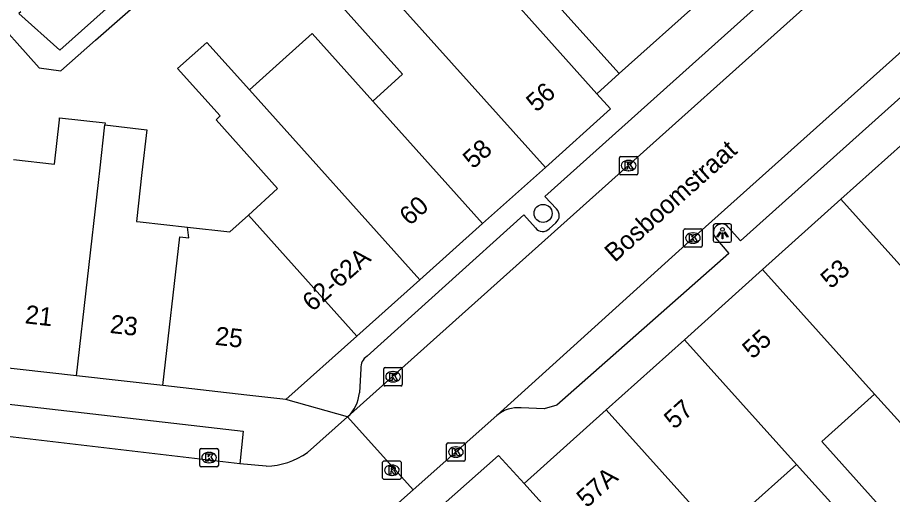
# Model space of a CAD drawing. Extents: x 162172 to 163187, y 382874 to 383684.
# Drawn here: x 162715.53 to 162762.94, y 383404.94 to 383430.81 of the extents above; entities that cross this region are included whole.
import ezdxf

# ---------------------------------------------------------------- set-up
doc = ezdxf.new("R2010")
doc.units = 0
for name, color, linetype in [('IMGEO_Boom', 7, 'Continuous'), ('IMGEO_Hek', 7, 'Continuous'), ('IMGEO_Kolk', 7, 'Continuous'), ('IMGEO_Lichtpunt', 7, 'Continuous'), ('IMGEO_Openbare_ruimte_label', 7, 'Continuous'), ('IMGEO_Pand', 7, 'Continuous'), ('IMGEO_Pand_nummerreeks', 7, 'Continuous'), ('IMGEO_Rijbaan_lokaal_open', 7, 'Continuous'), ('IMGEO_Rioolput', 7, 'Continuous'), ('IMGEO_Voetpad_open', 7, 'Continuous')]:
    doc.layers.add(name, color=color, linetype=linetype)

msp = doc.modelspace()

# ---------------------------------------------------------------- linework, layer by layer
at = {"layer": 'IMGEO_Boom'}
msp.add_circle((162744.01, 383420.19), 0.489, dxfattribs=at)
at = {"layer": 'IMGEO_Hek'}
msp.add_lwpolyline([(162746.923, 383426.68), (162748.132, 383427.77)], dxfattribs=at)
at = {"layer": 'IMGEO_Kolk'}
for p, q in [((162748.144, 383422.354), (162748.144, 383423.206)), ((162748.219, 383423.28), (162749.071, 383423.28)), ((162748.632, 383423.06), (162748.657, 383423.06)), ((162749.145, 383423.206), (162749.145, 383422.354)), ((162749.071, 383422.28), (162748.219, 383422.28)), ((162748.655, 383422.5), (162748.63, 383422.5)), ((162751.628, 383418.426), (162751.628, 383419.278)), ((162751.703, 383419.352), (162752.555, 383419.352)), ((162752.629, 383419.278), (162752.629, 383418.426)), ((162752.116, 383419.132), (162752.141, 383419.132)), ((162752.555, 383418.352), (162751.703, 383418.352)), ((162752.139, 383418.572), (162752.114, 383418.572)), ((162735.383, 383410.903), (162735.383, 383411.755)), ((162735.458, 383411.829), (162736.31, 383411.829)), ((162736.384, 383411.755), (162736.384, 383410.903)), ((162735.871, 383411.609), (162735.896, 383411.609)), ((162736.31, 383410.829), (162735.458, 383410.829)), ((162735.894, 383411.049), (162735.869, 383411.049)), ((162725.415, 383406.52), (162725.415, 383407.372)), ((162725.49, 383407.446), (162726.342, 383407.446)), ((162726.416, 383407.372), (162726.416, 383406.52)), ((162738.785, 383406.822), (162738.785, 383407.674)), ((162738.86, 383407.748), (162739.712, 383407.748)), ((162739.273, 383407.528), (162739.298, 383407.528)), ((162739.786, 383407.674), (162739.786, 383406.822)), ((162725.903, 383407.226), (162725.928, 383407.226)), ((162739.296, 383406.968), (162739.271, 383406.968)), ((162726.342, 383406.446), (162725.49, 383406.446)), ((162725.926, 383406.666), (162725.901, 383406.666)), ((162739.712, 383406.748), (162738.86, 383406.748))]:
    msp.add_line(p, q, dxfattribs=at)
for points in [[(162748.144, 383422.354), (162748.144, 383423.206)], [(162748.219, 383423.28), (162749.071, 383423.28)], [(162749.145, 383423.206), (162749.145, 383422.354)], [(162748.465, 383422.98), (162748.588, 383422.98), (162748.588, 383422.829), (162748.718, 383422.98), (162748.882, 383422.98), (162748.736, 383422.829), (162748.889, 383422.58), (162748.737, 383422.58), (162748.652, 383422.744), (162748.588, 383422.677), (162748.588, 383422.58), (162748.465, 383422.58), (162748.465, 383422.98)], [(162749.071, 383422.28), (162748.219, 383422.28)], [(162751.628, 383418.426), (162751.628, 383419.278)], [(162751.703, 383419.352), (162752.555, 383419.352)], [(162752.629, 383419.278), (162752.629, 383418.426)], [(162751.949, 383419.052), (162752.072, 383419.052), (162752.072, 383418.901), (162752.202, 383419.052), (162752.366, 383419.052), (162752.22, 383418.901), (162752.373, 383418.652), (162752.221, 383418.652), (162752.136, 383418.816), (162752.072, 383418.749), (162752.072, 383418.652), (162751.949, 383418.652), (162751.949, 383419.052)], [(162752.555, 383418.352), (162751.703, 383418.352)], [(162735.383, 383410.903), (162735.383, 383411.755)], [(162735.458, 383411.829), (162736.31, 383411.829)], [(162736.384, 383411.755), (162736.384, 383410.903)], [(162735.704, 383411.529), (162735.827, 383411.529), (162735.827, 383411.378), (162735.957, 383411.529), (162736.121, 383411.529), (162735.975, 383411.378), (162736.128, 383411.129), (162735.976, 383411.129), (162735.891, 383411.293), (162735.827, 383411.226), (162735.827, 383411.129), (162735.704, 383411.129), (162735.704, 383411.529)], [(162736.31, 383410.829), (162735.458, 383410.829)], [(162725.415, 383406.52), (162725.415, 383407.372)], [(162725.49, 383407.446), (162726.342, 383407.446)], [(162726.416, 383407.372), (162726.416, 383406.52)], [(162738.785, 383406.822), (162738.785, 383407.674)], [(162738.86, 383407.748), (162739.712, 383407.748)], [(162739.106, 383407.448), (162739.229, 383407.448), (162739.229, 383407.297), (162739.359, 383407.448), (162739.523, 383407.448), (162739.377, 383407.297), (162739.53, 383407.048), (162739.378, 383407.048), (162739.293, 383407.212), (162739.229, 383407.145), (162739.229, 383407.048), (162739.106, 383407.048), (162739.106, 383407.448)], [(162739.786, 383407.674), (162739.786, 383406.822)], [(162725.736, 383407.146), (162725.859, 383407.146), (162725.859, 383406.995), (162725.989, 383407.146), (162726.153, 383407.146), (162726.007, 383406.995), (162726.16, 383406.746), (162726.008, 383406.746), (162725.923, 383406.91), (162725.859, 383406.843), (162725.859, 383406.746), (162725.736, 383406.746), (162725.736, 383407.146)], [(162726.342, 383406.446), (162725.49, 383406.446)], [(162739.712, 383406.748), (162738.86, 383406.748)]]:
    msp.add_lwpolyline(points, dxfattribs=at)
for centre, start, end in [((162748.221, 383423.204), 91.552, 178.448), ((162748.221, 383423.204), 91.552, 178.448), ((162749.069, 383423.204), 1.552, 88.448), ((162749.069, 383423.204), 1.552, 88.448), ((162748.221, 383422.356), 181.552, 268.448), ((162748.221, 383422.356), 181.552, 268.448), ((162749.069, 383422.356), 271.552, 358.448), ((162749.069, 383422.356), 271.552, 358.448), ((162751.705, 383419.276), 91.552, 178.448), ((162751.705, 383419.276), 91.552, 178.448), ((162752.553, 383419.276), 1.552, 88.448), ((162752.553, 383419.276), 1.552, 88.448), ((162751.705, 383418.428), 181.552, 268.448), ((162751.705, 383418.428), 181.552, 268.448), ((162752.553, 383418.428), 271.552, 358.448), ((162752.553, 383418.428), 271.552, 358.448), ((162735.46, 383411.753), 91.552, 178.448), ((162735.46, 383411.753), 91.552, 178.448), ((162736.308, 383411.753), 1.552, 88.448), ((162736.308, 383411.753), 1.552, 88.448), ((162735.46, 383410.905), 181.552, 268.448), ((162735.46, 383410.905), 181.552, 268.448), ((162736.308, 383410.905), 271.552, 358.448), ((162736.308, 383410.905), 271.552, 358.448), ((162725.492, 383407.37), 91.552, 178.448), ((162725.492, 383407.37), 91.552, 178.448), ((162726.34, 383407.37), 1.552, 88.448), ((162726.34, 383407.37), 1.552, 88.448), ((162738.862, 383407.672), 91.552, 178.448), ((162738.862, 383407.672), 91.552, 178.448), ((162739.71, 383407.672), 1.552, 88.448), ((162739.71, 383407.672), 1.552, 88.448), ((162725.492, 383406.522), 181.552, 268.448), ((162725.492, 383406.522), 181.552, 268.448), ((162726.34, 383406.522), 271.552, 358.448), ((162726.34, 383406.522), 271.552, 358.448), ((162738.862, 383406.824), 181.552, 268.448), ((162738.862, 383406.824), 181.552, 268.448), ((162739.71, 383406.824), 271.552, 358.448), ((162739.71, 383406.824), 271.552, 358.448)]:
    msp.add_arc(centre, 0.0765, start, end, dxfattribs=at)
for centre, major_axis, ratio, start_param, end_param in [((162748.631, 383422.78), (-0.387, 0.002), 0.722429, 4.712389, 7.853982), ((162748.656, 383422.78), (-0.39, 0.002), 0.717154, 1.570796, 4.712389), ((162752.115, 383418.852), (-0.387, 0.002), 0.722429, 4.712389, 7.853982), ((162752.14, 383418.852), (-0.39, 0.002), 0.717154, 1.570796, 4.712389), ((162735.87, 383411.329), (-0.387, 0.002), 0.722429, 4.712389, 7.853982), ((162735.895, 383411.329), (-0.39, 0.002), 0.717154, 1.570796, 4.712389), ((162739.272, 383407.248), (-0.387, 0.002), 0.722429, 4.712389, 7.853982), ((162739.297, 383407.248), (-0.39, 0.002), 0.717154, 1.570796, 4.712389), ((162725.902, 383406.946), (-0.387, 0.002), 0.722429, 4.712389, 7.853982), ((162725.927, 383406.946), (-0.39, 0.002), 0.717154, 1.570796, 4.712389)]:
    msp.add_ellipse(centre, major_axis=major_axis, ratio=ratio, start_param=start_param, end_param=end_param, dxfattribs=at)
at = {"layer": 'IMGEO_Lichtpunt'}
for p, q in [((162753.232, 383419.523), (162753.232, 383418.716)), ((162753.232, 383419.523), (162753.232, 383418.716)), ((162754.134, 383419.618), (162753.326, 383419.618)), ((162754.134, 383419.618), (162753.326, 383419.618)), ((162754.228, 383418.716), (162754.228, 383419.523)), ((162754.228, 383418.716), (162754.228, 383419.523)), ((162753.326, 383418.622), (162754.134, 383418.622)), ((162753.326, 383418.622), (162754.134, 383418.622))]:
    msp.add_line(p, q, dxfattribs=at)
for points in [[(162753.606, 383419.187), (162753.645, 383419.159), (162753.457, 383418.897), (162753.419, 383418.924), (162753.606, 383419.187)], [(162753.708, 383419.139), (162753.755, 383419.139), (162753.755, 383418.817), (162753.708, 383418.817), (162753.708, 383419.139)], [(162753.818, 383419.159), (162753.856, 383419.186), (162754.043, 383418.924), (162754.004, 383418.896), (162753.818, 383419.159)]]:
    msp.add_lwpolyline(points, dxfattribs=at)
msp.add_circle((162753.731, 383419.321), 0.0994, dxfattribs=at)
for centre, start, end in [((162753.326, 383419.523), 90, 180), ((162753.326, 383419.523), 90, 180), ((162754.134, 383419.523), 0, 90), ((162754.134, 383419.523), 0, 90), ((162753.326, 383418.716), 180, 270), ((162753.326, 383418.716), 180, 270), ((162754.134, 383418.716), 270, 0), ((162754.134, 383418.716), 270, 360)]:
    msp.add_arc(centre, 0.0946, start, end, dxfattribs=at)
at = {"layer": 'IMGEO_Pand'}
for points in [[(162748.132, 383427.77), (162742.099, 383434.496)], [(162734.778, 383426.279), (162736.399, 383427.732), (162733.136, 383431.374), (162734.919, 383432.971)], [(162734.919, 383432.971), (162744.135, 383422.684)], [(162741.697, 383432.527), (162744.331, 383429.573), (162746.923, 383426.68)], [(162715.706, 383431.115), (162715.607, 383431.027), (162717.821, 383429.043), (162721.517, 383432.346)], [(162748.132, 383427.77), (162752.658, 383431.842)], [(162728.095, 383426.888), (162729.908, 383428.512), (162731.5, 383429.938), (162734.778, 383426.279)], [(162728.044, 383420.099), (162729.629, 383421.542), (162726.289, 383425.27), (162726.517, 383425.474), (162724.21, 383428.048), (162725.788, 383429.462), (162728.095, 383426.888)], [(162737.328, 383416.585), (162728.095, 383426.888)], [(162744.135, 383422.684), (162747.668, 383425.849), (162746.923, 383426.68)], [(162740.731, 383419.634), (162734.778, 383426.279)], [(162715.325, 383423.104), (162717.531, 383422.854), (162717.804, 383425.263), (162717.817, 383425.378), (162720.286, 383425.098), (162720.273, 383424.984)], [(162718.732, 383411.377), (162719.92, 383421.872), (162720.009, 383422.654), (162720.254, 383424.821), (162720.273, 383424.984)], [(162720.273, 383424.984), (162722.536, 383424.727), (162722.272, 383422.398), (162721.972, 383419.747), (162722.182, 383419.724), (162724.749, 383419.442)], [(162760.149, 383420.951), (162764.392, 383424.759)], [(162740.731, 383419.634), (162744.135, 383422.684)], [(162755.907, 383417.144), (162760.149, 383420.951)], [(162760.149, 383420.951), (162766.217, 383414.192)], [(162724.749, 383419.442), (162727.046, 383419.189), (162728.044, 383420.099)], [(162728.044, 383420.099), (162733.924, 383413.536)], [(162723.408, 383410.848), (162724.321, 383418.91), (162724.816, 383418.854), (162724.749, 383419.442)], [(162737.328, 383416.585), (162740.731, 383419.634)], [(162751.665, 383413.337), (162755.907, 383417.144)], [(162761.975, 383410.385), (162755.907, 383417.144)], [(162733.924, 383413.536), (162737.328, 383416.585)], [(162730.081, 383410.092), (162733.924, 383413.536)], [(162747.423, 383409.529), (162751.665, 383413.337)], [(162757.734, 383406.577), (162751.665, 383413.337)], [(162718.732, 383411.377), (162714.057, 383411.906)], [(162723.408, 383410.848), (162718.732, 383411.377)], [(162730.081, 383410.092), (162727.951, 383410.333), (162723.408, 383410.848)], [(162766.032, 383405.895), (162763.147, 383403.317), (162759.111, 383407.813), (162761.975, 383410.385)], [(162761.975, 383410.385), (162766.032, 383405.895)], [(162742.977, 383405.54), (162747.423, 383409.529)], [(162747.423, 383409.529), (162753.492, 383402.769)], [(162761.781, 383402.098), (162758.895, 383399.52), (162754.869, 383404.005), (162757.734, 383406.577)], [(162757.734, 383406.577), (162761.781, 383402.098)], [(162753.709, 383393.536), (162749.046, 383398.778), (162742.977, 383405.54)]]:
    msp.add_lwpolyline(points, dxfattribs=at)
at = {"layer": 'IMGEO_Rijbaan_lokaal_open'}
for points in [[(162741.498, 383409.238), (162752.129, 383418.852), (162795.051, 383457.315)], [(162772.219, 383443.956), (162733.422, 383409.153), (162733.42, 383409.152)], [(162727.575, 383406.608), (162691.943, 383410.803)], [(162733.42, 383409.152), (162731.239, 383407.228)], [(162733.42, 383409.152), (162736.967, 383405.198)], [(162741.498, 383409.238), (162736.967, 383405.198)], [(162729.014, 383406.474), (162727.575, 383406.608)], [(162736.967, 383405.198), (162733.903, 383402.466)]]:
    msp.add_lwpolyline(points, dxfattribs=at)
msp.add_arc((162728.858, 383410.593), 4.122, 272.1624, 305.2782, dxfattribs=at)
at = {"layer": 'IMGEO_Rioolput'}
for p, q in [((162735.315, 383405.838), (162735.315, 383406.69)), ((162735.39, 383406.764), (162736.242, 383406.764)), ((162735.803, 383406.544), (162735.828, 383406.544)), ((162736.316, 383406.69), (162736.316, 383405.838)), ((162735.826, 383405.984), (162735.801, 383405.984)), ((162736.242, 383405.764), (162735.39, 383405.764))]:
    msp.add_line(p, q, dxfattribs=at)
for points in [[(162735.315, 383405.838), (162735.315, 383406.69)], [(162735.39, 383406.764), (162736.242, 383406.764)], [(162735.904, 383406.462), (162735.652, 383406.464), (162735.652, 383406.064)], [(162736.316, 383406.69), (162736.316, 383405.838)], [(162735.652, 383406.064), (162735.776, 383406.064), (162735.776, 383406.226), (162735.787, 383406.226)], [(162735.83, 383406.383), (162735.776, 383406.383), (162735.776, 383406.302)], [(162735.776, 383406.302), (162735.828, 383406.302)], [(162735.834, 383406.197), (162735.905, 383406.064), (162736.045, 383406.064), (162735.98, 383406.19)], [(162736.242, 383405.764), (162735.39, 383405.764)]]:
    msp.add_lwpolyline(points, dxfattribs=at)
for centre, radius, start, end in [((162735.392, 383406.688), 0.0765, 91.552, 178.448), ((162735.392, 383406.688), 0.0765, 91.552, 178.448), ((162735.903, 383406.352), 0.109, 350.3612, 89.416), ((162736.24, 383406.688), 0.0765, 1.552, 88.448), ((162736.24, 383406.688), 0.0765, 1.552, 88.448), ((162735.786, 383406.173), 0.0533, 26.0293, 88.6989), ((162735.812, 383406.491), 0.19, 274.7715, 282.9687), ((162735.836, 383406.287), 0.0964, 77.0061, 93.1865), ((162735.85, 383406.344), 0.0378, 276.6634, 79.6772), ((162735.901, 383406.352), 0.112, 277.5842, 350.9817), ((162735.885, 383406.137), 0.108, 29.5134, 73.7905), ((162735.392, 383405.84), 0.0765, 181.552, 268.448), ((162735.392, 383405.84), 0.0765, 181.552, 268.448), ((162736.24, 383405.84), 0.0765, 271.552, 358.448), ((162736.24, 383405.84), 0.0765, 271.552, 358.448)]:
    msp.add_arc(centre, radius, start, end, dxfattribs=at)
for centre, major_axis, ratio, start_param, end_param in [((162735.802, 383406.264), (-0.387, 0.002), 0.722429, 4.712389, 7.853982), ((162735.827, 383406.264), (-0.39, 0.002), 0.717154, 1.570796, 4.712389)]:
    msp.add_ellipse(centre, major_axis=major_axis, ratio=ratio, start_param=start_param, end_param=end_param, dxfattribs=at)
at = {"layer": 'IMGEO_Voetpad_open'}
for points in [[(162700.525, 383419.608), (162713.853, 383431.266), (162716.715, 383428.083), (162717.873, 383427.924), (162719.751, 383429.576), (162729.561, 383438.208)], [(162757.265, 383431.639), (162756.625, 383432.343), (162744.101, 383421.107), (162744.734, 383420.428)], [(162766.494, 383430.718), (162767.216, 383429.929), (162754.709, 383418.707), (162754.048, 383419.447)], [(162746.923, 383426.68), (162748.132, 383427.77)], [(162743.606, 383419.402), (162742.975, 383420.103), (162734.474, 383412.442)], [(162744.698, 383419.685), (162744.349, 383419.359)], [(162753.36, 383418.862), (162754.077, 383418.006), (162744.757, 383409.795), (162744.065, 383409.585), (162742.828, 383409.64)], [(162734.128, 383411.775), (162734.056, 383410.462)], [(162701.898, 383411.367), (162727.754, 383408.381), (162727.575, 383406.608)], [(162733.42, 383409.152), (162730.081, 383410.092)], [(162736.389, 383402.443), (162741.599, 383407.069), (162742.977, 383405.54)]]:
    msp.add_lwpolyline(points, dxfattribs=at)
for centre, radius, start, end in [((162744.409, 383420.071), 0.482, 306.779, 47.6731), ((162743.995, 383419.686), 0.482, 216.1098, 317.2658), ((162753.696, 383419.164), 0.452, 38.8597, 221.8887), ((162734.905, 383411.795), 0.777, 123.6773, 181.4875), ((162732.069, 383410.617), 1.993, 312.677, 355.5302), ((162742.658, 383407.802), 1.846, 84.7088, 128.9266)]:
    msp.add_arc(centre, radius, start, end, dxfattribs=at)

# ---------------------------------------------------------------- texts
at = {"layer": 'IMGEO_Openbare_ruimte_label'}
msp.add_text('Bosboomstraat', height=1, rotation=41.8381, dxfattribs=at).set_placement((162747.897, 383417.5))
at = {"layer": 'IMGEO_Pand_nummerreeks'}
for s, rotation, p in [('56', 41.861, (162743.653, 383425.636)), ('58', 41.861, (162740.219, 383422.559)), ('60', 41.8603, (162736.783, 383419.481)), ('62-62A', 41.3618, (162731.515, 383414.819)), ('53', 41.9081, (162759.603, 383416.055)), ('21', 353.5428, (162715.905, 383414.232)), ('23', 353.5428, (162720.511, 383413.71)), ('25', 353.5533, (162726.206, 383413.066)), ('55', 41.9081, (162755.361, 383412.248)), ('57', 41.9081, (162751.119, 383408.441)), ('57A', 41.9061, (162746.383, 383404.188))]:
    msp.add_text(s, height=1, rotation=rotation, dxfattribs=at).set_placement(p)

doc.saveas('drawing.dxf')
